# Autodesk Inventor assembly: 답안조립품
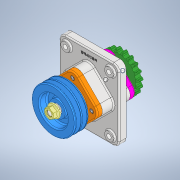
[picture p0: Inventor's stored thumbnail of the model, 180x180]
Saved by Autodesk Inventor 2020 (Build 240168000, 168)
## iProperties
Created: 2021-07
Part Number: 답안조립품
Document SubType Name: Assembly
Designer: Owner
Author: Owner
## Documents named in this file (16)
- C:\Users\Owner\Desktop\710707V1012\710707V1012\답안조립품.iam
- C:\Users\Owner\Desktop\710707V1012\710707V1012\본체.ipt
- C:\Users\Owner\Desktop\710707V1012\710707V1012\M16 너트.ipt
- C:\Users\Owner\Desktop\710707V1012\710707V1012\V-벨트풀리.ipt
- C:\Users\Owner\Desktop\710707V1012\710707V1012\멈춤나사 M4.ipt
- C:\Users\Owner\Desktop\710707V1012\710707V1012\베어링 6206.ipt
- C:\Users\Owner\Desktop\710707V1012\710707V1012\볼트 M6.ipt
- C:\Users\Owner\Desktop\710707V1012\710707V1012\부시.ipt
- C:\Users\Owner\Desktop\710707V1012\710707V1012\오일실 30x42x8.ipt
- C:\Users\Owner\Desktop\710707V1012\710707V1012\오일실 30x45x8.ipt
- C:\Users\Owner\Desktop\710707V1012\710707V1012\체인 스프로킷.ipt
- C:\Users\Owner\Desktop\710707V1012\710707V1012\축.ipt
- C:\Users\Owner\Desktop\710707V1012\710707V1012\커버A.ipt
- C:\Users\Owner\Desktop\710707V1012\710707V1012\커버B.ipt
- C:\Users\Owner\Desktop\710707V1012\710707V1012\키 6x6x18.ipt
- C:\Users\Owner\Desktop\710707V1012\710707V1012\키 6x6x20.ipt
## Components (3 placed, 2 different names)
1. M16 너트:1
2. V-벨트풀리:1
3. M16 너트:2
